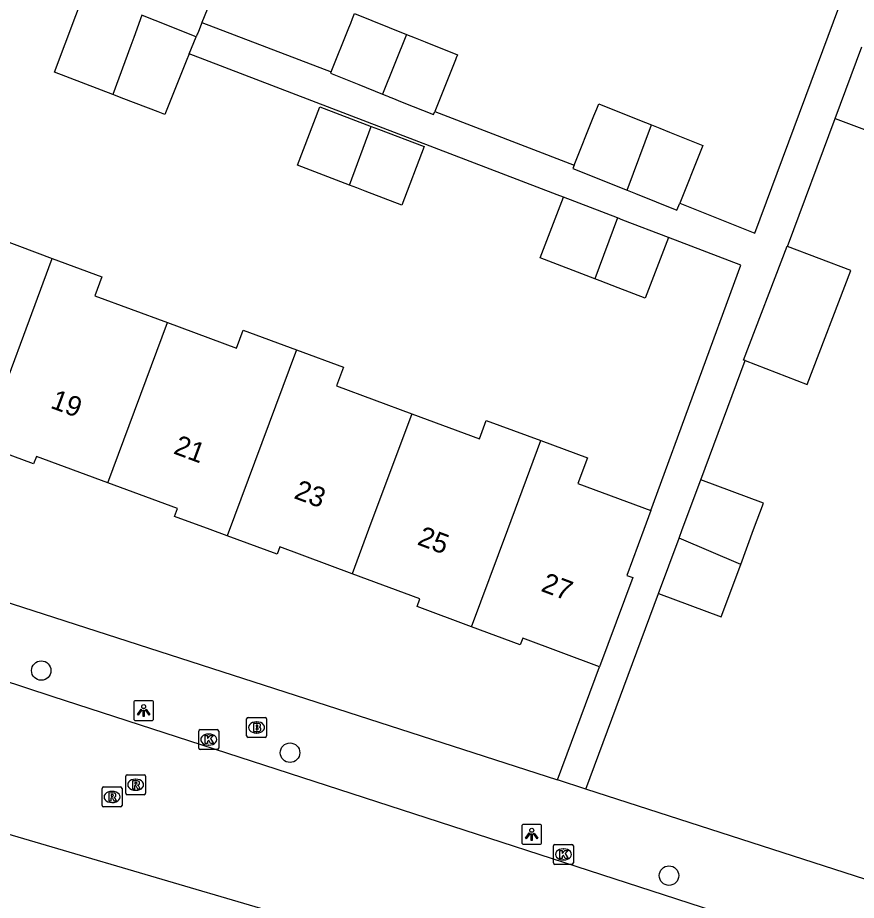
# Model space of a CAD drawing. Extents: x 163268 to 164360, y 381529 to 382285.
# Drawn here: x 163848.14 to 163890.23, y 381981.39 to 382025.7 of the extents above; entities that cross this region are included whole.
import ezdxf

# ---------------------------------------------------------------- set-up
doc = ezdxf.new("R2010")
doc.units = 0
for name, color, linetype in [('IMGEO_Boom', 7, 'Continuous'), ('IMGEO_Brandkraan', 7, 'Continuous'), ('IMGEO_Kolk', 7, 'Continuous'), ('IMGEO_Lichtpunt', 7, 'Continuous'), ('IMGEO_Pand', 7, 'Continuous'), ('IMGEO_Pand_nummerreeks', 7, 'Continuous'), ('IMGEO_Rijbaan_lokaal_open', 7, 'Continuous'), ('IMGEO_Rioolput', 7, 'Continuous'), ('IMGEO_Voetpad_open', 7, 'Continuous')]:
    doc.layers.add(name, color=color, linetype=linetype)

msp = doc.modelspace()

# ---------------------------------------------------------------- linework, layer by layer
at = {"layer": 'IMGEO_Boom'}
for centre in [(163849.321, 381992.923), (163861.808, 381988.799), (163880.83, 381982.63)]:
    msp.add_circle(centre, 0.489, dxfattribs=at)
at = {"layer": 'IMGEO_Brandkraan'}
for p, q in [((163859.63, 381989.642), (163859.63, 381990.494)), ((163859.705, 381990.568), (163860.557, 381990.568)), ((163860.631, 381990.494), (163860.631, 381989.642)), ((163860.118, 381990.348), (163860.143, 381990.348)), ((163860.557, 381989.568), (163859.705, 381989.568)), ((163860.141, 381989.788), (163860.116, 381989.788))]:
    msp.add_line(p, q, dxfattribs=at)
for points in [[(163859.63, 381989.642), (163859.63, 381990.494)], [(163859.705, 381990.568), (163860.557, 381990.568)], [(163860.631, 381990.494), (163860.631, 381989.642)], [(163859.978, 381990.268), (163859.978, 381989.868), (163860.191, 381989.868)], [(163860.209, 381990.268), (163859.978, 381990.268)], [(163860.157, 381990.187), (163860.103, 381990.187), (163860.103, 381990.111)], [(163860.103, 381990.111), (163860.156, 381990.111)], [(163860.165, 381990.035), (163860.103, 381990.035), (163860.103, 381989.954)], [(163860.557, 381989.568), (163859.705, 381989.568)], [(163860.103, 381989.954), (163860.165, 381989.954)]]:
    msp.add_lwpolyline(points, dxfattribs=at)
for centre, radius, start, end in [((163859.707, 381990.492), 0.0765, 91.552, 178.448), ((163859.707, 381990.492), 0.0765, 91.552, 178.448), ((163860.555, 381990.492), 0.0765, 1.552, 88.448), ((163860.555, 381990.492), 0.0765, 1.552, 88.448), ((163860.158, 381990.149), 0.0379, 267.8285, 90.9355), ((163860.166, 381989.994), 0.0404, 269.8759, 90.5077), ((163860.213, 381990.123), 0.145, 59.4692, 91.5367), ((163860.238, 381990.17), 0.0922, 285.5137, 58.1501), ((163860.243, 381989.978), 0.105, 301.3115, 78.989), ((163859.707, 381989.644), 0.0765, 181.552, 268.448), ((163859.707, 381989.644), 0.0765, 181.552, 268.448), ((163860.197, 381990.119), 0.251, 268.6676, 293.5347), ((163860.555, 381989.644), 0.0765, 271.552, 358.448), ((163860.555, 381989.644), 0.0765, 271.552, 358.448)]:
    msp.add_arc(centre, radius, start, end, dxfattribs=at)
for centre, major_axis, ratio, start_param, end_param in [((163860.117, 381990.068), (-0.387, 0.002), 0.722429, 4.712389, 7.853982), ((163860.142, 381990.068), (-0.39, 0.002), 0.717154, 1.570796, 4.712389)]:
    msp.add_ellipse(centre, major_axis=major_axis, ratio=ratio, start_param=start_param, end_param=end_param, dxfattribs=at)
at = {"layer": 'IMGEO_Kolk'}
for p, q in [((163857.226, 381989.033), (163857.226, 381989.885)), ((163857.301, 381989.959), (163858.153, 381989.959)), ((163857.714, 381989.739), (163857.739, 381989.739)), ((163858.227, 381989.885), (163858.227, 381989.033)), ((163857.737, 381989.179), (163857.712, 381989.179)), ((163858.153, 381988.959), (163857.301, 381988.959)), ((163875.032, 381983.268), (163875.032, 381984.12)), ((163875.107, 381984.194), (163875.959, 381984.194)), ((163875.52, 381983.974), (163875.545, 381983.974)), ((163876.033, 381984.12), (163876.033, 381983.268)), ((163875.543, 381983.414), (163875.518, 381983.414)), ((163875.959, 381983.194), (163875.107, 381983.194))]:
    msp.add_line(p, q, dxfattribs=at)
for points in [[(163857.226, 381989.033), (163857.226, 381989.885)], [(163857.301, 381989.959), (163858.153, 381989.959)], [(163857.547, 381989.659), (163857.67, 381989.659), (163857.67, 381989.508), (163857.8, 381989.659), (163857.964, 381989.659), (163857.818, 381989.508), (163857.971, 381989.259), (163857.819, 381989.259), (163857.734, 381989.423), (163857.67, 381989.356), (163857.67, 381989.259), (163857.547, 381989.259), (163857.547, 381989.659)], [(163858.227, 381989.885), (163858.227, 381989.033)], [(163858.153, 381988.959), (163857.301, 381988.959)], [(163875.032, 381983.268), (163875.032, 381984.12)], [(163875.107, 381984.194), (163875.959, 381984.194)], [(163875.353, 381983.894), (163875.476, 381983.894), (163875.476, 381983.743), (163875.606, 381983.894), (163875.77, 381983.894), (163875.624, 381983.743), (163875.777, 381983.494), (163875.625, 381983.494), (163875.54, 381983.658), (163875.476, 381983.591), (163875.476, 381983.494), (163875.353, 381983.494), (163875.353, 381983.894)], [(163876.033, 381984.12), (163876.033, 381983.268)], [(163875.959, 381983.194), (163875.107, 381983.194)]]:
    msp.add_lwpolyline(points, dxfattribs=at)
for centre, start, end in [((163857.303, 381989.883), 91.552, 178.448), ((163857.303, 381989.883), 91.552, 178.448), ((163858.151, 381989.883), 1.552, 88.448), ((163858.151, 381989.883), 1.552, 88.448), ((163857.303, 381989.035), 181.552, 268.448), ((163857.303, 381989.035), 181.552, 268.448), ((163858.151, 381989.035), 271.552, 358.448), ((163858.151, 381989.035), 271.552, 358.448), ((163875.109, 381984.118), 91.552, 178.448), ((163875.109, 381984.118), 91.552, 178.448), ((163875.957, 381984.118), 1.552, 88.448), ((163875.957, 381984.118), 1.552, 88.448), ((163875.109, 381983.27), 181.552, 268.448), ((163875.109, 381983.27), 181.552, 268.448), ((163875.957, 381983.27), 271.552, 358.448), ((163875.957, 381983.27), 271.552, 358.448)]:
    msp.add_arc(centre, 0.0765, start, end, dxfattribs=at)
for centre, major_axis, ratio, start_param, end_param in [((163857.713, 381989.459), (-0.387, 0.002), 0.722429, 4.712389, 7.853982), ((163857.738, 381989.459), (-0.39, 0.002), 0.717154, 1.570796, 4.712389), ((163875.519, 381983.694), (-0.387, 0.002), 0.722429, 4.712389, 7.853982), ((163875.544, 381983.694), (-0.39, 0.002), 0.717154, 1.570796, 4.712389)]:
    msp.add_ellipse(centre, major_axis=major_axis, ratio=ratio, start_param=start_param, end_param=end_param, dxfattribs=at)
at = {"layer": 'IMGEO_Lichtpunt'}
for p, q in [((163853.963, 381991.317), (163853.963, 381990.51)), ((163853.963, 381991.317), (163853.963, 381990.51)), ((163854.865, 381991.412), (163854.057, 381991.412)), ((163854.865, 381991.412), (163854.057, 381991.412)), ((163854.959, 381990.51), (163854.959, 381991.317)), ((163854.959, 381990.51), (163854.959, 381991.317)), ((163854.057, 381990.416), (163854.865, 381990.416)), ((163854.057, 381990.416), (163854.865, 381990.416)), ((163874.344, 381985.201), (163873.536, 381985.201)), ((163874.344, 381985.201), (163873.536, 381985.201)), ((163873.442, 381985.106), (163873.442, 381984.299)), ((163873.442, 381985.106), (163873.442, 381984.299)), ((163874.438, 381984.299), (163874.438, 381985.106)), ((163874.438, 381984.299), (163874.438, 381985.106)), ((163873.536, 381984.205), (163874.344, 381984.205)), ((163873.536, 381984.205), (163874.344, 381984.205))]:
    msp.add_line(p, q, dxfattribs=at)
for points in [[(163854.337, 381990.981), (163854.376, 381990.953), (163854.188, 381990.691), (163854.15, 381990.718), (163854.337, 381990.981)], [(163854.439, 381990.933), (163854.486, 381990.933), (163854.486, 381990.611), (163854.439, 381990.611), (163854.439, 381990.933)], [(163854.549, 381990.953), (163854.587, 381990.98), (163854.774, 381990.718), (163854.735, 381990.69), (163854.549, 381990.953)], [(163873.816, 381984.77), (163873.855, 381984.742), (163873.667, 381984.48), (163873.629, 381984.507), (163873.816, 381984.77)], [(163873.918, 381984.722), (163873.965, 381984.722), (163873.965, 381984.4), (163873.918, 381984.4), (163873.918, 381984.722)], [(163874.028, 381984.742), (163874.066, 381984.769), (163874.253, 381984.507), (163874.214, 381984.479), (163874.028, 381984.742)]]:
    msp.add_lwpolyline(points, dxfattribs=at)
for centre in [(163854.462, 381991.115), (163873.941, 381984.904)]:
    msp.add_circle(centre, 0.0994, dxfattribs=at)
for centre, start, end in [((163854.057, 381991.317), 90, 180), ((163854.057, 381991.317), 90, 180), ((163854.865, 381991.317), 0, 90), ((163854.865, 381991.317), 0, 90), ((163854.057, 381990.51), 180, 270), ((163854.057, 381990.51), 180, 270), ((163854.865, 381990.51), 270, 0), ((163854.865, 381990.51), 270, 360), ((163873.536, 381985.106), 90, 180), ((163873.536, 381985.106), 90, 180), ((163874.344, 381985.106), 0, 90), ((163874.344, 381985.106), 0, 90), ((163873.536, 381984.299), 180, 270), ((163873.536, 381984.299), 180, 270), ((163874.344, 381984.299), 270, 0), ((163874.344, 381984.299), 270, 360)]:
    msp.add_arc(centre, 0.0946, start, end, dxfattribs=at)
at = {"layer": 'IMGEO_Pand'}
for points in [[(163855.66, 382029.291), (163858.471, 382028.162), (163858.252, 382027.616), (163858.176, 382027.427), (163857.388, 382025.461)], [(163852.919, 382021.838), (163849.99, 382022.966), (163851.053, 382025.819), (163851.488, 382026.987)], [(163863.874, 382022.976), (163864.767, 382025.198), (163864.861, 382025.431), (163864.951, 382025.656), (163865.052, 382025.906), (163867.65, 382024.863)], [(163854.371, 382025.83), (163853.962, 382024.704), (163853.815, 382024.301), (163852.919, 382021.838)], [(163857.096, 382024.734), (163855.047, 382025.558), (163854.739, 382025.682), (163854.371, 382025.83)], [(163857.388, 382025.461), (163857.368, 382025.412), (163857.24, 382025.095), (163857.175, 382024.932), (163857.15, 382024.869), (163857.096, 382024.734)], [(163856.747, 382023.885), (163856.975, 382024.453), (163857.096, 382024.734)], [(163867.65, 382024.863), (163866.445, 382021.864)], [(163867.65, 382024.863), (163867.873, 382024.774), (163868.093, 382024.685), (163868.334, 382024.588), (163868.589, 382024.486), (163870.214, 382023.834), (163870.154, 382023.684), (163870.113, 382023.583), (163869.071, 382020.986)], [(163889.167, 382020.634), (163890.507, 382024.239)], [(163856.747, 382023.885), (163856.602, 382023.526), (163855.524, 382020.839), (163855.181, 382020.97), (163853.471, 382021.626), (163852.919, 382021.838)], [(163863.874, 382022.976), (163863.847, 382022.908), (163865.255, 382022.342), (163866.445, 382021.864)], [(163889.167, 382020.634), (163892.325, 382019.459), (163893.615, 382022.929)], [(163866.445, 382021.864), (163866.668, 382021.774), (163866.745, 382021.743), (163866.815, 382021.715), (163866.925, 382021.671), (163867.43, 382021.468), (163869.01, 382020.833), (163869.071, 382020.986)], [(163864.794, 382017.301), (163862.182, 382018.302), (163863.305, 382021.233), (163865.889, 382020.243)], [(163876.069, 382018.305), (163877.059, 382020.769), (163877.205, 382021.132), (163877.304, 382021.377), (163879.099, 382020.656), (163879.65, 382020.435), (163879.947, 382020.316)], [(163865.889, 382020.243), (163866.252, 382020.104), (163868.541, 382019.227), (163867.417, 382016.296), (163865.58, 382017), (163865.157, 382017.162), (163864.794, 382017.301)], [(163864.794, 382017.301), (163865.889, 382020.243)], [(163878.728, 382017.037), (163879.947, 382020.316)], [(163879.947, 382020.316), (163880.367, 382020.147), (163880.853, 382019.952), (163882.528, 382019.279), (163882.43, 382019.034), (163881.372, 382016.397)], [(163876.069, 382018.305), (163876, 382018.133), (163878.728, 382017.037)], [(163878.728, 382017.037), (163879.147, 382016.869), (163881.226, 382016.034), (163881.372, 382016.397)], [(163877.109, 382012.587), (163874.364, 382013.639), (163875.532, 382016.689)], [(163878.248, 382015.648), (163875.532, 382016.689)], [(163878.248, 382015.648), (163877.109, 382012.587)], [(163880.809, 382014.667), (163878.519, 382015.544), (163878.248, 382015.648)], [(163843.38, 382014.931), (163846.979, 382013.596), (163847.335, 382014.558), (163849.873, 382013.616)], [(163880.809, 382014.667), (163879.64, 382011.618), (163878.285, 382012.137), (163877.38, 382012.483), (163877.109, 382012.587)], [(163884.649, 382008.486), (163884.573, 382008.515), (163886.764, 382014.229), (163886.782, 382014.222)], [(163884.649, 382008.486), (163887.771, 382007.288), (163889.961, 382013.003), (163886.782, 382014.222)], [(163846.386, 382004.246), (163849.873, 382013.616)], [(163849.873, 382013.616), (163852.365, 382012.692), (163852.013, 382011.743), (163855.655, 382010.392)], [(163852.662, 382002.351), (163855.655, 382010.392)], [(163855.655, 382010.392), (163859.125, 382009.104), (163859.464, 382010.018), (163862.13, 382009.029)], [(163862.13, 382009.029), (163858.653, 381999.686)], [(163862.13, 382009.029), (163864.484, 382008.156), (163864.138, 382007.222), (163867.918, 382005.82)], [(163867.918, 382005.82), (163865.752, 382000), (163864.928, 381997.785)], [(163867.918, 382005.82), (163871.313, 382004.56), (163871.656, 382005.486), (163874.398, 382004.469)], [(163852.662, 382002.351), (163849.082, 382003.679), (163848.94, 382003.298), (163846.386, 382004.246)], [(163870.921, 381995.126), (163872.735, 382000), (163874.398, 382004.469)], [(163874.398, 382004.469), (163876.734, 382003.602), (163876.256, 382002.322), (163879.916, 382000.963)], [(163881.333, 381999.563), (163881.495, 382000), (163882.422, 382002.497)], [(163884.432, 381998.256), (163885.079, 382000), (163885.572, 382001.328), (163882.422, 382002.497)], [(163858.653, 381999.686), (163857.801, 382000), (163856.014, 382000.659), (163856.16, 382001.053), (163852.662, 382002.351)], [(163879.916, 382000.963), (163879.562, 382000), (163878.716, 381997.702), (163879.012, 381997.592), (163877.35, 381993.114)], [(163864.928, 381997.785), (163861.294, 381999.134), (163861.156, 381998.763), (163858.653, 381999.686)], [(163880.303, 381996.787), (163881.333, 381999.563)], [(163884.432, 381998.256), (163881.333, 381999.563)], [(163880.303, 381996.787), (163883.453, 381995.618), (163884.432, 381998.256)], [(163870.921, 381995.126), (163868.184, 381996.141), (163868.326, 381996.524), (163864.928, 381997.785)], [(163877.35, 381993.114), (163873.49, 381994.546), (163873.368, 381994.218), (163870.921, 381995.126)]]:
    msp.add_lwpolyline(points, dxfattribs=at)
at = {"layer": 'IMGEO_Rijbaan_lokaal_open'}
for points in [[(163757.318, 382021.706), (163762.591, 382019.997), (163809.167, 382005.041), (163831.384, 381997.714), (163849.853, 381991.631), (163896.886, 381976.383)], [(163860.342, 381980.985), (163844.613, 381985.6)]]:
    msp.add_lwpolyline(points, dxfattribs=at)
at = {"layer": 'IMGEO_Rioolput'}
for p, q in [((163853.559, 381986.766), (163853.559, 381987.618)), ((163853.634, 381987.692), (163854.486, 381987.692)), ((163854.047, 381987.472), (163854.072, 381987.472)), ((163854.56, 381987.618), (163854.56, 381986.766)), ((163852.373, 381986.153), (163852.373, 381987.005)), ((163852.448, 381987.079), (163853.3, 381987.079)), ((163853.374, 381987.005), (163853.374, 381986.153)), ((163854.07, 381986.912), (163854.045, 381986.912)), ((163852.861, 381986.859), (163852.886, 381986.859)), ((163854.486, 381986.692), (163853.634, 381986.692)), ((163853.3, 381986.079), (163852.448, 381986.079)), ((163852.884, 381986.299), (163852.859, 381986.299))]:
    msp.add_line(p, q, dxfattribs=at)
for points in [[(163853.559, 381986.766), (163853.559, 381987.618)], [(163853.634, 381987.692), (163854.486, 381987.692)], [(163854.148, 381987.39), (163853.896, 381987.392), (163853.896, 381986.992)], [(163854.56, 381987.618), (163854.56, 381986.766)], [(163852.373, 381986.153), (163852.373, 381987.005)], [(163852.448, 381987.079), (163853.3, 381987.079)], [(163853.374, 381987.005), (163853.374, 381986.153)], [(163853.896, 381986.992), (163854.02, 381986.992), (163854.02, 381987.154), (163854.031, 381987.154)], [(163854.074, 381987.311), (163854.02, 381987.311), (163854.02, 381987.23)], [(163854.02, 381987.23), (163854.072, 381987.23)], [(163854.078, 381987.125), (163854.149, 381986.992), (163854.289, 381986.992), (163854.224, 381987.118)], [(163852.962, 381986.777), (163852.71, 381986.779), (163852.71, 381986.379)], [(163852.71, 381986.379), (163852.834, 381986.379), (163852.834, 381986.541), (163852.845, 381986.541)], [(163852.888, 381986.698), (163852.834, 381986.698), (163852.834, 381986.617)], [(163852.834, 381986.617), (163852.886, 381986.617)], [(163852.892, 381986.512), (163852.963, 381986.379), (163853.103, 381986.379), (163853.038, 381986.505)], [(163854.486, 381986.692), (163853.634, 381986.692)], [(163853.3, 381986.079), (163852.448, 381986.079)]]:
    msp.add_lwpolyline(points, dxfattribs=at)
for centre, radius, start, end in [((163853.636, 381987.616), 0.0765, 91.552, 178.448), ((163853.636, 381987.616), 0.0765, 91.552, 178.448), ((163854.147, 381987.28), 0.109, 350.3612, 89.416), ((163854.484, 381987.616), 0.0765, 1.552, 88.448), ((163854.484, 381987.616), 0.0765, 1.552, 88.448), ((163852.45, 381987.003), 0.0765, 91.552, 178.448), ((163852.45, 381987.003), 0.0765, 91.552, 178.448), ((163853.298, 381987.003), 0.0765, 1.552, 88.448), ((163853.298, 381987.003), 0.0765, 1.552, 88.448), ((163854.03, 381987.101), 0.0533, 26.0293, 88.6989), ((163854.056, 381987.419), 0.19, 274.7715, 282.9687), ((163854.08, 381987.215), 0.0964, 77.0061, 93.1865), ((163854.094, 381987.272), 0.0378, 276.6634, 79.6772), ((163854.145, 381987.28), 0.112, 277.5842, 350.9817), ((163854.129, 381987.065), 0.108, 29.5134, 73.7905), ((163852.844, 381986.488), 0.0533, 26.0293, 88.6989), ((163852.87, 381986.806), 0.19, 274.7715, 282.9687), ((163852.894, 381986.602), 0.0964, 77.0061, 93.1865), ((163852.908, 381986.659), 0.0378, 276.6634, 79.6772), ((163852.961, 381986.667), 0.109, 350.3612, 89.416), ((163852.959, 381986.667), 0.112, 277.5842, 350.9817), ((163852.943, 381986.452), 0.108, 29.5134, 73.7905), ((163853.636, 381986.768), 0.0765, 181.552, 268.448), ((163853.636, 381986.768), 0.0765, 181.552, 268.448), ((163854.484, 381986.768), 0.0765, 271.552, 358.448), ((163854.484, 381986.768), 0.0765, 271.552, 358.448), ((163852.45, 381986.155), 0.0765, 181.552, 268.448), ((163852.45, 381986.155), 0.0765, 181.552, 268.448), ((163853.298, 381986.155), 0.0765, 271.552, 358.448), ((163853.298, 381986.155), 0.0765, 271.552, 358.448)]:
    msp.add_arc(centre, radius, start, end, dxfattribs=at)
for centre, major_axis, ratio, start_param, end_param in [((163854.046, 381987.192), (-0.387, 0.002), 0.722429, 4.712389, 7.853982), ((163854.071, 381987.192), (-0.39, 0.002), 0.717154, 1.570796, 4.712389), ((163852.86, 381986.579), (-0.387, 0.002), 0.722429, 4.712389, 7.853982), ((163852.885, 381986.579), (-0.39, 0.002), 0.717154, 1.570796, 4.712389)]:
    msp.add_ellipse(centre, major_axis=major_axis, ratio=ratio, start_param=start_param, end_param=end_param, dxfattribs=at)
at = {"layer": 'IMGEO_Voetpad_open'}
for points in [[(163881.372, 382016.397), (163885.14, 382014.885), (163889.945, 382027.81)], [(163857.388, 382025.461), (163863.874, 382022.976)], [(163875.532, 382016.689), (163875.214, 382016.811), (163856.747, 382023.885)], [(163869.071, 382020.986), (163876.069, 382018.305)], [(163886.782, 382014.222), (163889.167, 382020.634)], [(163784.545, 382016.624), (163836.291, 382000), (163875.242, 381987.433)], [(163879.916, 382000.963), (163884.442, 382013.276), (163880.809, 382014.667)], [(163882.422, 382002.497), (163884.649, 382008.486)], [(163876.662, 381986.975), (163880.303, 381996.787)], [(163875.242, 381987.433), (163877.35, 381993.114)], [(163876.662, 381986.975), (163875.242, 381987.433)], [(163899.009, 381979.765), (163876.662, 381986.975)]]:
    msp.add_lwpolyline(points, dxfattribs=at)

# ---------------------------------------------------------------- texts
at = {"layer": 'IMGEO_Pand_nummerreeks'}
for s, rotation, p in [('19', 339.6423, (163849.732, 382006.127)), ('21', 339.6423, (163855.908, 382003.835)), ('23', 339.6423, (163861.957, 382001.59)), ('25', 339.3916, (163868.147, 381999.267)), ('27', 339.3916, (163874.358, 381996.931))]:
    msp.add_text(s, height=1, rotation=rotation, dxfattribs=at).set_placement(p)

doc.saveas('drawing.dxf')
